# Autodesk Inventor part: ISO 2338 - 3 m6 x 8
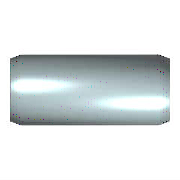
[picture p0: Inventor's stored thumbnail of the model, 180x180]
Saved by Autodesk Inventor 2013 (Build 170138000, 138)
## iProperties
Created: 2012-02
Part Number: ISO 2338 - 3 m6 x 8
Material: Stainless Steel, Austenitic
Description: Parallel Pin
Document SubType Name: Modeling
Standard: ISO 2338
Designer: rYan
Standards Organization: DIN
Language: en-US
Size Designation: 3 m6 x 8
Categories: <MemberInstance><Categories><Category DisplayName="Fasteners" InternalName="e4da775c-781d-43d5-af7c-5136215cf5a6" Mnemonic="FSTN"><Category DisplayName="Pins" I
Density: 8.03 g/cm^3
IsCustomPart: 0
Author: rYan
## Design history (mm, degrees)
sketch "Sketch"
  geometry: C1 r 1.5 at (0, 0); 1 further point
  constraints: 1 centre point, 1 coincident
  dimensions: "d1" = 3 diameter of C1 (= NND)
extrude "Body" new body sketch "Sketch" distance "d2" = 8 (= NLG); taper "d3" = 0 deg
body "Solid1"
chamfer "Chamfer1" distance "d4" = 0.5 (= PHH); stored, may be unused: angle "d5" = 15 deg (= FAWI), second distance "d11" = 0.5 (= PHH)
chamfer "Chamfer2" distance "d8" = 0.5 (= PHH); stored, may be unused: angle "d9" = 15 deg (= FAWI), second distance "d12" = 0.5 (= PHH)
other parameters: "NND" = 3 [user parameter; used in 1 equation term], "NLG" = 8 [user parameter; used in 1 equation term], "PHH" = 0.5 [user parameter; used in 4 equation terms], "FAWI" = 15 deg [user parameter; used in 2 equation terms], "d13" = 0, "d15" = 0, "d16" = 0, "KAH" = 0 [user parameter]
